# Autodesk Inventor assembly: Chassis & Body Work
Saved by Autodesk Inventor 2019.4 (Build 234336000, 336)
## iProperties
Created: 2020-04
Part Number: Chassis & Body Work
Document SubType Name: Assembly
Designer: Administrator
Title: Chassis & Body Work
Author: Administrator
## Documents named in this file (10)
- c:\worker\convert-fusion-r03\tmp\job-1\8\output\files\d342e430-10cf-4fa0-a064-3c3295007a1f\Chassis & Body Work.iam
- c:\worker\convert-fusion-r03\tmp\job-1\8\output\files\d342e430-10cf-4fa0-a064-3c3295007a1f\Bottom plate v8.ipt
- c:\worker\convert-fusion-r03\tmp\job-1\8\output\files\d342e430-10cf-4fa0-a064-3c3295007a1f\45x45 rounded v13.ipt
- c:\worker\convert-fusion-r03\tmp\job-1\8\output\files\d342e430-10cf-4fa0-a064-3c3295007a1f\Top plate v6.ipt
- c:\worker\convert-fusion-r03\tmp\job-1\8\output\files\d342e430-10cf-4fa0-a064-3c3295007a1f\40x40 L=500 v4.ipt
- c:\worker\convert-fusion-r03\tmp\job-1\8\output\files\d342e430-10cf-4fa0-a064-3c3295007a1f\40x40 L=400 v4.ipt
- c:\worker\convert-fusion-r03\tmp\job-1\8\output\files\d342e430-10cf-4fa0-a064-3c3295007a1f\Front plate v3.ipt
- c:\worker\convert-fusion-r03\tmp\job-1\8\output\files\d342e430-10cf-4fa0-a064-3c3295007a1f\Side plate v3.ipt
- c:\worker\convert-fusion-r03\tmp\job-1\8\output\files\d342e430-10cf-4fa0-a064-3c3295007a1f\Backplate v2.ipt
- c:\worker\convert-fusion-r03\tmp\job-1\8\output\files\d342e430-10cf-4fa0-a064-3c3295007a1f\45x45 corner piece v3.ipt
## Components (17 placed, 9 different names)
1. Bottom plate v8:1
2. 45x45 rounded v13:1
3. 45x45 rounded v13:2
4. 45x45 rounded v13:3
5. 45x45 rounded v13:4
6. Top plate v6:1
7. 40x40 L=500 v4:1
8. 40x40 L=500 v4:2
9. 40x40 L=400 v4:1
10. 40x40 L=400 v4:2
11. Front plate v3:1
12. 40x40 L=400 v4:4
13. Side plate v3:1
14. Side plate v3:2
15. Backplate v2:1
16. 45x45 corner piece v3:1
17. 45x45 corner piece v3:2
